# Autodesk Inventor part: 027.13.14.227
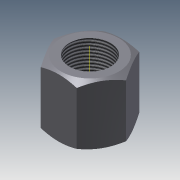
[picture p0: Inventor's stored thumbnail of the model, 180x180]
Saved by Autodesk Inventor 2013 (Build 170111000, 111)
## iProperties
Shininess: 64.0
Length Units: 11269
Angle Units: 11279
Time Units: 11290
Mass Units: 11283
Length Display Precision: 3
Angle Display Precision: 2
Created: 2002-02
Part Number: 027.13.14.227
Material: Steel, Mild
Document SubType Name: Modeling
Designer: SOleg
Density: 7.86 g/cm^3
Density: 0.0
Volumn: 0.0
Area: 0.0
PropertySet Name: Model Information
Control State: 0
Master: False
Checked Out: True
Checked Out Date: 2008-10-15
Last Check In Date: 2008-10-15
Author: SOleg
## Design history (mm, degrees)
sketch "Sketch1"
  geometry: L1 (11.836, 20.5)-(23.671, 0); L2 (23.671, 0)-(11.836, -20.5); L3 (11.836, -20.5)-(-11.836, -20.5); L4 (-11.836, -20.5)-(-23.671, 0); L5 (-23.671, 0)-(-11.836, 20.5); L6 (-11.836, 20.5)-(11.836, 20.5); C1 r 13.5 at (0, 0); 3 further points
  constraints: 12 end point, 2 coincident, 1 centre point, 1 midpoint, 1 vertical alignment, 13 other
  dimensions: "d1" = 27 diameter of C1
extrude "Extrusion1" new body sketch "Sketch1" distance "d2" = 40; taper "d3" = 0 deg
node "РабОсь1"
sketch "Sketch2"
  geometry: L1 (-19, 40)-(-32.041, 40); L2 (0, 45)-(0, -1.383); L3 (-19, 40)-(-32.041, 32.471); L4 (-32.041, 32.471)-(-32.041, 40); L5 (20.5, 0)-(20.5, 40) reference; L6 (20.5, 20)-(-24.004, 20); L7 (-19, 0)-(-32.041, 0); L8 (-19, 0)-(-32.041, 7.529); L9 (-32.041, 7.529)-(-32.041, 0); L10 (0, -10.66)-(0, 54.277) reference; L11 (13.5, 0)-(-13.5, 0) reference; L12 (20.5, 0)-(0, 0) reference; L13 (0, 0)-(-20.5, 0) reference; L14 (-20.5, 0)-(0, 0) reference; L15 (0, 0)-(20.5, 0) reference; L16 (-13.5, 40)-(13.5, 40) reference; L17 (20.5, 40)-(0, 40) reference; L18 (0, 40)-(20.5, 40) reference; L19 (-20.5, 40)-(0, 40) reference; L20 (0, 40)-(-20.5, 40) reference
  constraints: 16 end point, 3 collinear, 3 symmetric about line, 2 perpendicular, 1 midpoint, 3 other
  dimensions: "d5" = 30 deg angle of L1 L3; "d9" = 38 diameter of L7.start L2
revolve "Revolution1" sketch "Sketch2" stored, may be unused: angle "d6" = 90 deg
thread "Thread1" dims "d7" = 10, "d8" = 0
body "Solid1"
node "Спроецированная петля1"
node "Спроецированная петля2"
other parameters: "d0" = 41
